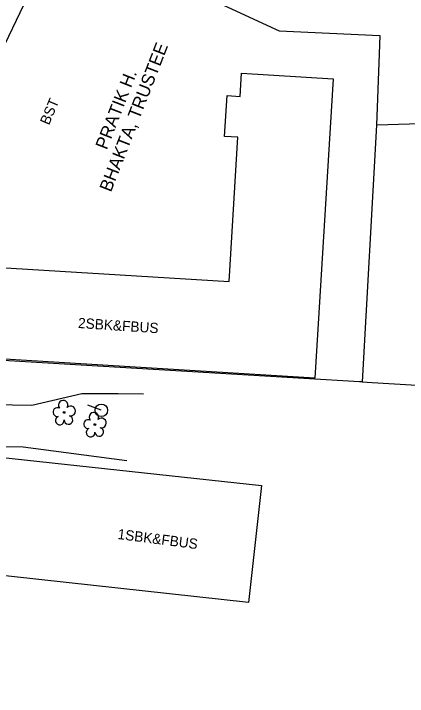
# Model space of a CAD drawing. Extents: x 945964 to 948456, y 631061 to 636061.
# Drawn here: x 947557.8 to 947711.8, y 634401.3 to 634668.2 of the extents above; entities that cross this region are included whole.
import ezdxf

# ---------------------------------------------------------------- set-up
doc = ezdxf.new("R2010")
doc.units = 0
for name, color, linetype in [('Exist Building', 7, 'Continuous'), ('Exist Building Text', 7, 'Continuous'), ('Exist Property Line', 7, 'Continuous'), ('Exist Property Owner Text', 7, 'Continuous'), ('Exist Right of Way Line', 7, 'Continuous'), ('Exist Roads EOP Other Text', 7, 'Continuous'), ('Exist Utilities Power Pole CELL', 7, 'Continuous'), ('Exist Vegetation Hedge Row', 7, 'Continuous'), ('Exist Vegetation Tree CELL', 7, 'Continuous')]:
    doc.layers.add(name, color=color, linetype=linetype)

# ---------------------------------------------------------------- blocks, each defined once
blk = doc.blocks.new('EXIST UTILITIES POWER POLE')
at = {"layer": 'Exist Utilities Power Pole CELL'}
for q in [(0, 0.1125), (0, 0)]:
    blk.add_line((0, 0), q, dxfattribs=at)
blk.add_circle((0, 0), 0.049, dxfattribs=at)

msp = doc.modelspace()

# ---------------------------------------------------------------- linework, layer by layer
at = {"layer": 'Exist Building'}
for points in [[(947533.24, 634570.16), (947642.08, 634563.46), (947645.55, 634619.91), (947640.35, 634620.23), (947641.33, 634636.15), (947646.37, 634635.84), (947646.93, 634644.89), (947682.78, 634642.68), (947675.59, 634525.72), (947535.1, 634534.36), (947536.26, 634553.22), (947527.95, 634553.73), (947528.84, 634568.29), (947533.11, 634568.02)], [(947552.31, 634494.88), (947654.71, 634483.72), (947649.74, 634438.09), (947547.34, 634449.25)]]:
    msp.add_lwpolyline(points, close=True, dxfattribs=at)
at = {"layer": 'Exist Property Line'}
msp.add_line((947699.81, 634624.62), (947694.12, 634524.25), dxfattribs=at)
for points in [[(947850.17, 634868.56), (947842.19, 634849.94), (947840.62, 634846.31), (947839.38, 634843.38), (947861.38, 634831.06), (947771.75, 634626.88), (947704.19, 634624.75), (947699.81, 634624.62)], [(947575.82, 634701.25), (947661.75, 634661.5), (947701, 634659.62), (947700.75, 634652.5), (947699.81, 634624.62)], [(947694.12, 634524.25), (947693.06, 634524.31), (947496.95, 634536.07)], [(947694.12, 634524.25), (947698.12, 634524), (947835.38, 634515.75), (948072.25, 634501.62)]]:
    msp.add_lwpolyline(points, dxfattribs=at)
at = {"layer": 'Exist Right of Way Line'}
msp.add_line((947661.98, 634881.73), (947432.63, 634401.34), dxfattribs=at)
at = {"layer": 'Exist Vegetation Hedge Row'}
for points in [[(947549.69, 634515.37), (947564.96, 634515.17), (947584.44, 634519.69), (947598.69, 634519.71), (947608.56, 634519.64)], [(947602.13, 634493.46), (947561.5, 634498.7), (947553.49, 634498.84)]]:
    msp.add_lwpolyline(points, dxfattribs=at)
at = {"layer": 'Exist Vegetation Tree CELL'}
for p, q in [((947577.57, 634512.3), (947577.57, 634512.3)), ((947589.61, 634507.6), (947589.61, 634507.6))]:
    msp.add_line(p, q, dxfattribs=at)
for centre in [(947577.57, 634512.3), (947589.61, 634507.6)]:
    msp.add_circle(centre, 0.326, dxfattribs=at)
for centre, radius, start, end in [((947577.18, 634515.17), 1.86, 330.1651, 219.7134), ((947574.96, 634512.45), 1.73, 62.6636, 279.3457), ((947580.11, 634512.89), 1.9, 257.1011, 134.1999), ((947579.24, 634509.4), 1.7, 181.2822, 74.56), ((947589.23, 634510.47), 1.86, 330.1651, 219.7134), ((947575.86, 634509.18), 1.69, 111.5671, 6.231), ((947587.01, 634507.75), 1.73, 62.6636, 279.3457), ((947592.16, 634508.19), 1.9, 257.1011, 134.1999), ((947587.91, 634504.48), 1.69, 111.5671, 6.231), ((947591.28, 634504.7), 1.7, 181.2822, 74.56)]:
    msp.add_arc(centre, radius, start, end, dxfattribs=at)

# ---------------------------------------------------------------- block references
at = {"layer": 'Exist Utilities Power Pole CELL', "xscale": 50.000000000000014, "yscale": 50.00000000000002, "rotation": 68.6175894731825}
msp.add_blockref('EXIST UTILITIES POWER POLE', (947592.11, 634513.15), dxfattribs=at)

# ---------------------------------------------------------------- texts
at = {"layer": 'Exist Building Text'}
for s, rotation, p in [('2SBK&FBUS', 356.2075, (947582.92, 634545.34)), ('1SBK&FBUS', 352.6754, (947598.32, 634462.88))]:
    msp.add_text(s, height=4, rotation=rotation, dxfattribs=at).set_placement(p)
at = {"layer": 'Exist Property Owner Text'}
for s, p in [('BHAKTA, TRUSTEE', (947595.88, 634598.17)), ('PRATIK H. ', (947594.28, 634614.7))]:
    msp.add_text(s, height=5, rotation=68.6661, dxfattribs=at).set_placement(p)
at = {"layer": 'Exist Roads EOP Other Text'}
msp.add_text('BST', height=4, rotation=67.2562, dxfattribs=at).set_placement((947571.66, 634624.39))

doc.saveas('drawing.dxf')
